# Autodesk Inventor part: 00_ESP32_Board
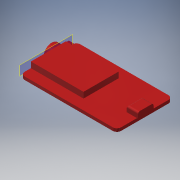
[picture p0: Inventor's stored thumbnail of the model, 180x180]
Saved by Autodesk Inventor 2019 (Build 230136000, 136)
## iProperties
Created: 2021-09
Part Number: 00_ESP32_Board
Material: Generisch
Document SubType Name: Modeling
Designer: Muriel
Density: 1 g/cm^3
Appearance: Hellrot
Author: Muriel
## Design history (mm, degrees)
sketch "Skizze1"
  geometry: L1 (-21.35, -13.5)-(21.35, -13.5); L2 (23.35, -11.5)-(23.35, 11.5); L3 (21.35, 13.5)-(-21.35, 13.5); L4 (-23.35, 11.5)-(-23.35, -11.5); L5 (-23.35, -13.5)-(23.35, 13.5); L6 (23.35, -13.5)-(-23.35, 13.5); A1 r 2 centre (21.35, 11.5) between (23.35, 11.5) and (21.35, 13.5); A2 r 2 centre (21.35, -11.5) between (21.35, -13.5) and (23.35, -11.5); A3 r 2 centre (-21.35, -11.5) between (-23.35, -11.5) and (-21.35, -13.5); A4 r 2 centre (-21.35, 11.5) between (-21.35, 13.5) and (-23.35, 11.5); 1 further point
  constraints: 12 end point, 8 point on circle, 8 point on line, 8 tangent, 4 centre point, 3 equal radius, 2 midpoint, 2 parallel, 1 horizontal, 1 perpendicular
  dimensions: "d0" = 46.7 distance of L6.end L5.end; "d1" = 27 distance of L5.end L6.start; "d2" = 2 radius of A1 (derived)
extrude "Extrusion1" new body sketch "Skizze1" distance "d3" = 1.5; taper "d4" = 0 deg
sketch "Skizze2"
  geometry: L1 (-21.35, -13.5)-(21.35, -13.5) reference; L2 (23.35, -11.5)-(23.35, 11.5) reference; L3 (21.35, 13.5)-(-21.35, 13.5) reference; L4 (-23.35, 11.5)-(-23.35, -11.5) reference; L5 (18.35, -3.75)-(23.85, -3.75); L6 (23.85, -3.75)-(23.85, 3.75); L7 (23.85, 3.75)-(18.35, 3.75); L8 (18.35, 3.75)-(18.35, -3.75); L9 (18.35, -3.75)-(23.85, 3.75); L10 (23.85, -3.75)-(18.35, 3.75); A1 r 2 centre (21.35, -11.5) between (21.35, -13.5) and (23.35, -11.5) reference; A2 r 2 centre (21.35, 11.5) between (23.35, 11.5) and (21.35, 13.5) reference; A3 r 2 centre (-21.35, 11.5) between (-21.35, 13.5) and (-23.35, 11.5) reference; A4 r 2 centre (-21.35, -11.5) between (-23.35, -11.5) and (-21.35, -13.5) reference; 2 further points
  constraints: 12 end point, 2 midpoint, 2 parallel, 1 horizontal, 1 perpendicular
  dimensions: "d5" = 5.5 distance of L7.end L6.end; "d6" = 7.5 distance of L6.end L5.end; "d7" = 0.5 distance between parallel lines of L6 L2
extrude "Extrusion2" join sketch "Skizze2" distance "d8" = 2.8; taper "d9" = 0 deg
fillet "Rundung1" dims "d10" = 1
sketch "Skizze3"
  geometry: L1 (-21.35, 13.5)-(21.35, 13.5) reference; L2 (-23.35, -11.5)-(-23.35, 11.5) reference; L3 (21.35, -13.5)-(-21.35, -13.5) reference; L4 (23.35, 11.5)-(23.35, -11.5) reference; L5 (2.15, -8.5)-(-23.35, -8.5); L6 (-23.35, -8.5)-(-23.35, 8.5); L7 (-23.35, 8.5)-(2.15, 8.5); L8 (2.15, 8.5)-(2.15, -8.5); L9 (2.15, -8.5)-(-23.35, 8.5); L10 (-23.35, -8.5)-(2.15, 8.5); A1 r 2 centre (-21.35, 11.5) between (-21.35, 13.5) and (-23.35, 11.5) reference; A2 r 2 centre (-21.35, -11.5) between (-23.35, -11.5) and (-21.35, -13.5) reference; A3 r 2 centre (21.35, -11.5) between (21.35, -13.5) and (23.35, -11.5) reference; A4 r 2 centre (21.35, 11.5) between (23.35, 11.5) and (21.35, 13.5) reference; 3 further points
  constraints: 12 end point, 4 midpoint, 2 parallel, 1 horizontal, 1 perpendicular
  dimensions: "d11" = 25.5 distance of L6.end L7.end; "d12" = 17 distance of L5.end L6.end
extrude "Extrusion3" join sketch "Skizze3" distance "d13" = 2.8; taper "d14" = 0 deg
sketch "Skizze5"
  geometry: L1 (-21.35, 13.5)-(21.35, 13.5) reference; L2 (-23.35, -11.5)-(-23.35, 11.5) reference; L3 (21.35, -13.5)-(-21.35, -13.5) reference; L4 (23.35, 11.5)-(23.35, -11.5) reference; L5 (-5.569, -8.25)-(-10.35, -8.25); L6 (-10.35, -8.25)-(-10.35, 8.25); L7 (-10.35, 8.25)-(-5.569, 8.25); L8 (-5.569, 8.25)-(-5.569, -8.25); L9 (-5.569, -8.25)-(-10.35, 8.25); L10 (-10.35, -8.25)-(-5.569, 8.25); L11 (15.35, -7.5)-(0.35, -7.5); L12 (0.35, -7.5)-(0.35, 7.5); L13 (0.35, 7.5)-(15.35, 7.5); L14 (15.35, 7.5)-(15.35, -7.5); L15 (15.35, -7.5)-(0.35, 7.5); L16 (0.35, -7.5)-(15.35, 7.5); A1 r 2 centre (-21.35, 11.5) between (-21.35, 13.5) and (-23.35, 11.5) reference; A2 r 2 centre (-21.35, -11.5) between (-23.35, -11.5) and (-21.35, -13.5) reference; A3 r 2 centre (21.35, -11.5) between (21.35, -13.5) and (23.35, -11.5) reference; A4 r 2 centre (21.35, 11.5) between (23.35, 11.5) and (21.35, 13.5) reference; 3 further points
  constraints: 24 end point, 4 midpoint, 4 parallel, 2 horizontal, 2 perpendicular
  dimensions: "d23" = 15 distance of L12.end L13.end; "d24" = 15 distance of L11.end L12.end; "d25" = 13 distance between parallel lines of L6 L2; "d26" = 16.5 distance between parallel lines of L5 L7; "d27" = 8 distance between parallel lines of L4 L14
extrude "Extrusion5" join sketch "Skizze5" distance "d28" = 2; taper "d29" = 0 deg
workplane "Arbeitsebene1"
sketch "Skizze8"
  geometry: L1 (7.5, 0.8)-(-1.5, 0.8); L2 (-1.5, 0.8)-(-1.5, -8.2); L3 (-1.5, -8.2)-(7.5, -8.2); L4 (7.5, -8.2)-(7.5, 0.8); L5 (7.5, 0.8)-(-1.5, -8.2); L6 (-1.5, 0.8)-(7.5, -8.2); L7 (0, 0)-(23, 0) reference; L8 (3, 4.3)-(20, 4.3) reference; L9 (19.75, -2)-(3.25, -2) reference; L10 (0, 0)-(-2, 0) reference; L11 (-2, 0)-(-2, 1.5) reference; 2 further points
  constraints: 12 end point, 2 midpoint, 2 parallel, 1 horizontal, 1 perpendicular
  dimensions: "d40" = 9 distance of L3.end L2.end; "d41" = 9 distance of L2.end L1.end; "d53" = 0.8 distance between parallel lines of L10 L1; "d54" = 0.5 distance between parallel lines of L2 L11
extrude "Extrusion8" join sketch "Skizze8" distance "d43" = 2.1; taper "d44" = 0 deg
sketch "Skizze9"
  geometry: L1 (7.5, 0.8)-(-1.5, 0.8) reference; L2 (-1.5, 0.8)-(-1.5, -8.2) reference; L3 (-1.5, -8.2)-(7.5, -8.2) reference; L4 (7.5, -8.2)-(7.5, 0.8) reference; C1 r 4 at (3, -3.7); 1 further point
  constraints: 1 centre point
  dimensions: "d45" = 8 diameter of C1; "d49" = 4.5 distance from line of C1.centre L1; "d50" = 4.5 distance from line of L4 C1.centre
extrude "Extrusion9" join sketch "Skizze9" distance "d46" = 3.8; taper "d47" = 0 deg
node "Volumenkörper1"
node "Projizierte Kontur1"
node "Projizierte Kontur2"
node "Projizierte Kontur4"
node "Projizierte Kontur8"
other parameters: "d39" = 1
